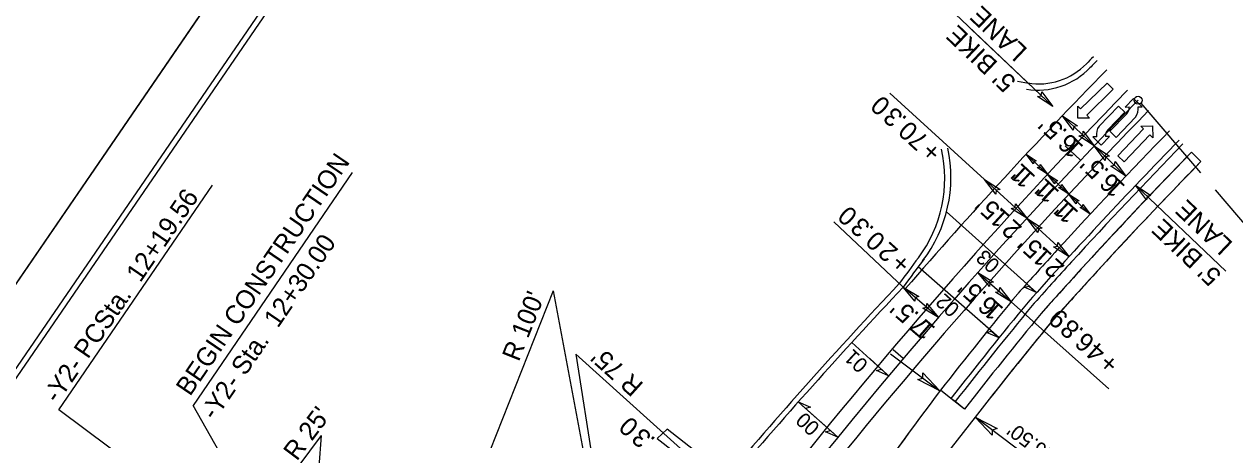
# Model space of a CAD drawing. Extents: x 1975573 to 1977432, y 778300 to 780514.
# Drawn here: x 1976079 to 1976648, y 779581 to 779776 of the extents above; entities that cross this region are included whole.
import ezdxf

# ---------------------------------------------------------------- set-up
doc = ezdxf.new("R2010")
doc.units = 0
for name, color, linetype in [('Prop Conc 2ft 6in Curb and Gutter', 7, 'Continuous'), ('Prop Conc 4in Sidewalk', 7, 'Continuous'), ('Prop Dimension', 7, 'Continuous'), ('Prop Dimension Text', 7, 'Continuous'), ('Prop EOT', 7, 'Continuous'), ('Prop Horizontal Alignment', 7, 'Continuous'), ('Prop Horizontal Alignment Station Label', 7, 'Continuous'), ('Prop Horizontal Alignment Tick Large', 7, 'Continuous'), ('Prop Horizontal Alignment Tick Small', 7, 'Continuous'), ('Prop Lane Arrow CELL', 7, 'Continuous'), ('Prop Lane Lines', 7, 'Continuous'), ('Prop Superelevation  Arrow CELL', 7, 'Continuous'), ('Prop Superelevation Label', 7, 'Continuous'), ('Prop Terminator CELL', 7, 'Continuous'), ('Sheet Cutting Line CELL', 7, 'Continuous'), ('Sheet Plot Border Inside CELL', 7, 'Continuous'), ('Sheet Plot Border Outside CELL', 7, 'Continuous'), ('Sheet Typical CELL', 7, 'Continuous'), ('Typical Terminator CELL', 7, 'Continuous')]:
    doc.layers.add(name, color=color, linetype=linetype)

# ---------------------------------------------------------------- blocks, each defined once
blk = doc.blocks.new('TERMINATOR')
at = {"layer": 'Typical Terminator CELL'}
blk.add_lwpolyline([(-0.469, 0.081), (0, 0), (-0.471, -0.083), (-0.411, 0)], close=True, dxfattribs=at)

msp = doc.modelspace()

# ---------------------------------------------------------------- linework, layer by layer
at = {"layer": 'Prop Conc 2ft 6in Curb and Gutter'}
msp.add_line((1976545.66, 779749.13), (1976550.8, 779748.26), dxfattribs=at)
for centre, radius, start, end in [((1978303.2, 778082.63), 2404.37, 135.73946, 135.84984), ((1976555.6, 779779.15), 31.25, 260.4237, 315.8498), ((1978303.2, 778082.63), 2345.62, 135.73946, 137.60087), ((1976448.91, 779703.56), 62.5, 323.2499, 12.6226), ((1978429.52, 778224.57), 2409.39, 143.24986, 143.60985), ((1978303.2, 778082.63), 2345.62, 137.60087, 138.28391), ((1978239.96, 778006.13), 2403.74, 136.72119, 139.7323), ((1978364.54, 778155.19), 2345.04, 140.59771, 142.01273)]:
    msp.add_arc(centre, radius, start, end, dxfattribs=at)
at = {"layer": 'Prop Conc 4in Sidewalk'}
for p, q in [((1976631.83, 779711.41), (1976627.35, 779715.77)), ((1976631.83, 779711.41), (1976627.35, 779715.77)), ((1976514.33, 779600.08), (1976509.41, 779603.93)), ((1976520.72, 779595.06), (1976514.33, 779600.08)), ((1976380.92, 779585.56), (1976376.28, 779581.25)), ((1976409.06, 779563.62), (1976380.92, 779585.56)), ((1976376.28, 779581.25), (1976404.98, 779558.88))]:
    msp.add_line(p, q, dxfattribs=at)
for points in [[(1976561.18, 779635.59), (1976561.17, 779635.6)], [(1976561.51, 779635.99), (1976561.51, 779635.99)], [(1976520.72, 779595.06), (1976514.33, 779600.08), (1976509.41, 779603.93)], [(1976509.41, 779603.93), (1976509.41, 779603.93)], [(1976520.72, 779595.06), (1976516.3, 779598.53), (1976514.33, 779600.08)]]:
    msp.add_lwpolyline(points, dxfattribs=at)
for centre, radius, start, end in [((1978303.2, 778082.63), 2340, 135.73946, 138.27742), ((1978303.2, 778082.63), 2340, 135.73946, 137.58605), ((1978303.2, 778082.63), 2340, 135.8138, 137.58605), ((1978303.2, 778082.63), 2333.75, 135.73946, 138.27119), ((1978303.2, 778082.63), 2333.75, 135.73946, 137.56744), ((1978303.2, 778082.63), 2340, 137.58605, 138.27742), ((1978303.2, 778082.63), 2340, 137.58605, 138.27742), ((1978303.2, 778082.63), 2333.75, 137.56744, 138.28391), ((1978364.54, 778155.19), 2339.42, 140.6042, 142.01325), ((1978364.54, 778155.19), 2339.42, 140.6042, 142.01325), ((1978364.54, 778155.19), 2339.42, 140.6042, 142.01325), ((1978364.54, 778155.19), 2333.17, 140.6042, 142.01244), ((1978364.54, 778155.19), 2333.17, 140.61692, 142.01244), ((1978303.2, 778082.63), 2333.75, 138.2743, 138.28391), ((1978364.54, 778155.19), 2333.17, 140.6042, 140.60732), ((1978392.04, 778191.34), 2353.66, 143.11825, 144.71902), ((1978392.04, 778191.34), 2353.66, 143.11825, 144.7184), ((1978364.97, 778155.71), 2333.19, 142.02902, 143.82111), ((1978364.97, 778155.71), 2333.19, 142.02902, 143.82111)]:
    msp.add_arc(centre, radius, start, end, dxfattribs=at)
at = {"layer": 'Prop Dimension'}
for p, q in [((1976485.91, 779621), (1976509.14, 779603.58)), ((1976507.11, 779600.86), (1976507.04, 779600.78)), ((1976523.6, 779588.49), (1976523.54, 779588.4)), ((1976561.64, 779564.2), (1976525.64, 779591.2))]:
    msp.add_line(p, q, dxfattribs=at)
at = {"layer": 'Prop Dimension Text'}
for p, q in [((1976516.31, 779780.83), (1976562.16, 779737.26)), ((1976524.02, 779773.51), (1976562.16, 779737.26)), ((1976485.63, 779743.57), (1976530.14, 779702.9)), ((1976581.64, 779718.74), (1976566.69, 779732.95)), ((1976596.59, 779704.54), (1976581.64, 779718.74)), ((1976549.62, 779714.8), (1976559.68, 779705.43)), ((1976549.98, 779684.77), (1976530.14, 779702.9)), ((1976559.68, 779705.43), (1976569.75, 779696.06)), ((1976569.75, 779696.06), (1976579.81, 779686.69)), ((1976601.12, 779700.23), (1976643.6, 779659.86)), ((1976554.56, 779649.78), (1976512.21, 779687.74)), ((1976569.82, 779666.64), (1976549.98, 779684.77)), ((1976459.32, 779683.08), (1976491.9, 779652.41)), ((1976536.92, 779628.55), (1976498.92, 779661.89)), ((1976527.03, 779659.28), (1976542.58, 779645.42)), ((1976327.31, 779650.68), (1976281.28, 779534.47)), ((1976327.31, 779650.68), (1976350.38, 779527.83)), ((1976508.43, 779638.08), (1976491.9, 779652.41)), ((1976588.53, 779604.52), (1976542.61, 779645.46)), ((1976337.97, 779620.81), (1976352.55, 779528.21)), ((1976337.97, 779620.81), (1976407.71, 779558.17)), ((1976218.28, 779582.67), (1976199.52, 779557.67)), ((1976218.28, 779582.67), (1976215.95, 779551.51))]:
    msp.add_line(p, q, dxfattribs=at)
at = {"layer": 'Prop EOT'}
for centre, radius, start, end in [((1978303.2, 778082.63), 2401.88, 135.73946, 135.87087), ((1976555, 779779.1), 34.15, 261.1736, 316.5998), ((1978303.2, 778082.63), 2348.12, 135.73946, 138.28391), ((1976449.17, 779704.12), 65.14, 322.7217, 12.0583), ((1978429.52, 778224.57), 2406.89, 143.22203, 143.61344), ((1978239.96, 778006.13), 2401.24, 136.7176, 139.73317), ((1978364.54, 778155.19), 2347.54, 140.59771, 142.01251), ((1978385.78, 778195.91), 2345.91, 143.11561, 144.72166)]:
    msp.add_arc(centre, radius, start, end, dxfattribs=at)
at = {"layer": 'Prop Horizontal Alignment'}
msp.add_arc((1978303.2, 778082.63), 2375, 135.73946, 152.1381, dxfattribs=at)
at = {"layer": 'Prop Horizontal Alignment Station Label'}
for p, q in [((1976603.63, 779738.89), (1976631.61, 779706.14)), ((1976232.78, 779706.22), (1976158.07, 779596.64)), ((1976094.98, 779594.64), (1976167.22, 779700.3)), ((1976638.47, 779698.11), (1976724.43, 779597.46)), ((1976182.82, 779529.12), (1976094.98, 779594.64)), ((1976197.33, 779527.36), (1976158.07, 779596.64))]:
    msp.add_line(p, q, dxfattribs=at)
msp.add_circle((1976602.29, 779740.2), 1.88, dxfattribs=at)
at = {"layer": 'Prop Horizontal Alignment Tick Large'}
msp.add_line((1976575.24, 779711.98), (1976567.97, 779718.84), dxfattribs=at)
at = {"layer": 'Prop Horizontal Alignment Tick Small'}
msp.add_line((1976491.92, 779618.82), (1976487.15, 779622.87), dxfattribs=at)
at = {"layer": 'Prop Lane Arrow CELL'}
for p, q in [((1976575.25, 779736.11), (1976587.77, 779748.33)), ((1976587.77, 779748.33), (1976590.65, 779745.38)), ((1976590.65, 779745.38), (1976578.13, 779733.16)), ((1976573.91, 779731.84), (1976573.94, 779737.45)), ((1976573.94, 779737.45), (1976575.25, 779736.11)), ((1976593.14, 779737.44), (1976583.95, 779727.98)), ((1976596.1, 779734.56), (1976593.14, 779737.44)), ((1976600.16, 779741.07), (1976596.24, 779737.04)), ((1976596.24, 779737.04), (1976598.09, 779737.07)), ((1976604.15, 779737.2), (1976600.16, 779741.07)), ((1976602.25, 779737.13), (1976604.15, 779737.2)), ((1976579.44, 779731.81), (1976573.91, 779731.84)), ((1976578.13, 779733.16), (1976579.44, 779731.81)), ((1976588.12, 779726.36), (1976596.1, 779734.56)), ((1976596.95, 779733.82), (1976588.97, 779725.62)), ((1976591.93, 779722.75), (1976601.12, 779732.2)), ((1976588.97, 779725.62), (1976591.93, 779722.75)), ((1976592.77, 779714.15), (1976604.91, 779726.76)), ((1976603.56, 779728.06), (1976609.08, 779728.2)), ((1976604.91, 779726.76), (1976603.56, 779728.06)), ((1976609.08, 779728.2), (1976609.23, 779722.59)), ((1976582.82, 779723.06), (1976580.97, 779723.03)), ((1976580.97, 779723.03), (1976584.87, 779719.15)), ((1976584.87, 779719.15), (1976588.83, 779723.14)), ((1976588.83, 779723.14), (1976586.98, 779723.12)), ((1976607.88, 779723.89), (1976595.74, 779711.29)), ((1976609.23, 779722.59), (1976607.88, 779723.89)), ((1976595.74, 779711.29), (1976592.77, 779714.15))]:
    msp.add_line(p, q, dxfattribs=at)
for centre, radius, start, end in [((1976594.02, 779736.71), 4.09, 315.8193, 5.4775), ((1976595.78, 779736.04), 6.57, 324.4954, 9.8071), ((1976589.28, 779724.18), 6.57, 144.4954, 189.8071), ((1976591.04, 779723.51), 4.09, 135.8193, 185.4775)]:
    msp.add_arc(centre, radius, start, end, dxfattribs=at)
at = {"layer": 'Prop Lane Lines'}
for centre, radius, start, end in [((1978303.2, 778082.63), 2395.62, 135.73946, 139.08605), ((1978303.2, 778082.63), 2381.88, 135.73946, 141.94983), ((1978303.2, 778082.63), 2368.12, 135.73946, 141.23948), ((1978303.2, 778082.63), 2354.38, 135.73946, 137.61142), ((1978303.2, 778082.63), 2354.38, 137.61142, 138.28391), ((1978364.54, 778155.19), 2353.79, 140.59771, 142.01248)]:
    msp.add_arc(centre, radius, start, end, dxfattribs=at)
at = {"layer": 'Prop Superelevation  Arrow CELL'}
for p, q in [((1976554.56, 779649.78), (1976545.63, 779657.79)), ((1976536.92, 779628.55), (1976527.9, 779636.46)), ((1976485.02, 779610.65), (1976476.16, 779618.74)), ((1976442.43, 779598.45), (1976451.42, 779590.5)), ((1976461.21, 779581.86), (1976452.21, 779589.81))]:
    msp.add_line(p, q, dxfattribs=at)
for points in [[(1976554.56, 779649.78), (1976548.76, 779652.3), (1976551.12, 779652.87)], [(1976536.92, 779628.55), (1976531.09, 779631), (1976533.44, 779631.6)], [(1976485.02, 779610.65), (1976479.24, 779613.22), (1976481.6, 779613.77)], [(1976442.43, 779598.45), (1976448.25, 779595.97), (1976445.9, 779595.38)], [(1976461.21, 779581.86), (1976455.39, 779584.33), (1976457.74, 779584.92)]]:
    msp.add_lwpolyline(points, close=True, dxfattribs=at)
at = {"layer": 'Prop Superelevation Label'}
for p, q in [((1976485.02, 779610.65), (1976467.77, 779626.41)), ((1976461.21, 779581.86), (1976442.43, 779598.45))]:
    msp.add_line(p, q, dxfattribs=at)
at = {"layer": 'Prop Terminator CELL'}
for points in [[(1976557.05, 779744.12), (1976562.16, 779737.26), (1976554.98, 779742.02), (1976556.79, 779742.36)], [(1976571.81, 779726.09), (1976566.69, 779732.95), (1976573.88, 779728.2), (1976572.06, 779727.85)], [(1976576.53, 779725.61), (1976581.64, 779718.74), (1976574.46, 779723.5), (1976576.27, 779723.85)], [(1976586.76, 779711.88), (1976581.64, 779718.74), (1976588.83, 779713.99), (1976587.01, 779713.64)], [(1976553.07, 779710.26), (1976549.62, 779714.8), (1976554.44, 779711.68), (1976553.23, 779711.43)], [(1976556.22, 779709.97), (1976559.68, 779705.43), (1976554.86, 779708.55), (1976556.07, 779708.79)], [(1976591.48, 779711.4), (1976596.59, 779704.54), (1976589.41, 779709.29), (1976591.22, 779709.64)], [(1976535.39, 779696.13), (1976530.14, 779702.9), (1976537.41, 779698.28), (1976535.6, 779697.9)], [(1976563.14, 779700.89), (1976559.68, 779705.43), (1976564.5, 779702.31), (1976563.3, 779702.07)], [(1976566.29, 779700.6), (1976569.75, 779696.06), (1976564.92, 779699.18), (1976566.13, 779699.43)], [(1976573.2, 779691.52), (1976569.75, 779696.06), (1976574.57, 779692.94), (1976573.36, 779692.7)], [(1976606.24, 779693.37), (1976601.12, 779700.23), (1976608.31, 779695.47), (1976606.49, 779695.13)], [(1976544.73, 779691.53), (1976549.98, 779684.77), (1976542.7, 779689.38), (1976544.51, 779689.76)], [(1976576.35, 779691.24), (1976579.81, 779686.69), (1976574.99, 779689.82), (1976576.2, 779690.06)], [(1976555.22, 779678), (1976549.98, 779684.77), (1976557.25, 779680.15), (1976555.44, 779679.77)], [(1976564.57, 779673.4), (1976569.82, 779666.64), (1976562.54, 779671.25), (1976564.35, 779671.63)], [(1976532.36, 779652.59), (1976527.03, 779659.28), (1976534.36, 779654.76), (1976532.56, 779654.36)], [(1976497.32, 779645.78), (1976491.9, 779652.41), (1976499.29, 779647.98), (1976497.49, 779647.56)], [(1976537.24, 779652.12), (1976542.58, 779645.42), (1976535.24, 779649.95), (1976537.05, 779650.35)], [(1976503, 779644.7), (1976508.43, 779638.08), (1976501.03, 779642.5), (1976502.83, 779642.93)]]:
    msp.add_lwpolyline(points, close=True, dxfattribs=at)
at = {"layer": 'Sheet Cutting Line CELL'}
msp.add_line((1976524.64, 780310.68), (1975572.77, 778921.51), dxfattribs=at)
at = {"layer": 'Sheet Plot Border Inside CELL'}
msp.add_lwpolyline([(1976540.62, 780294.27), (1975598.63, 778919.54), (1976469.01, 778323.15), (1977410.99, 779697.88)], close=True, dxfattribs=at)
at = {"layer": 'Sheet Plot Border Outside CELL'}
msp.add_lwpolyline([(1976524.64, 780310.68), (1975572.77, 778921.51), (1976480.18, 778299.74), (1977432.06, 779688.9)], close=True, dxfattribs=at)
at = {"layer": 'Sheet Typical CELL'}
msp.add_lwpolyline([(1976535.66, 780282.52), (1975687.78, 779045.14), (1976553.95, 778451.63), (1977401.82, 779689.01)], close=True, dxfattribs=at)

# ---------------------------------------------------------------- block references
at = {"layer": 'Prop Dimension'}
for p, xscale, yscale, rotation in [((1976509.14, 779603.58), 24.499999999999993, 24.499999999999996, -36.8736862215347), ((1976525.64, 779591.2), 24.499999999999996, 24.499999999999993, 143.12631377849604)]:
    msp.add_blockref('TERMINATOR', p, dxfattribs=dict(at, xscale=xscale, yscale=yscale, rotation=rotation))

# ---------------------------------------------------------------- texts
msp.add_text("16.50'", height=7, rotation=143.1263, dxfattribs=at).set_placement((1976564.37, 779574.09))
at = {"layer": 'Prop Dimension Text'}
for s, rotation, p in [('LANE', 136.4577, (1976550.78, 779764.09)), ("5' BIKE", 136.4577, (1976545.48, 779749.52)), ('0', 137.5783, (1976486.5, 779738.66)), ('3', 137.5783, (1976492.4, 779733.27)), ('.', 137.5783, (1976494.13, 779731.69)), ('5', 136.4577, (1976567.83, 779727.21)), ('0', 137.5783, (1976499.52, 779726.76)), ('7', 137.5783, (1976504.4, 779722.3)), ("'", 136.4577, (1976562.33, 779732.43)), ('.', 136.4577, (1976569.52, 779725.59)), ('6', 136.4577, (1976574.62, 779720.75)), ('1', 136.4577, (1976577.11, 779718.38)), ('+', 137.5783, (1976510.5, 779716.72)), ('1', 137.0538, (1976552.02, 779706.58)), ('1', 137.0538, (1976554.54, 779704.24)), ("'", 136.4577, (1976581.91, 779713.88)), ('5', 136.4577, (1976587.4, 779708.66)), ('.', 136.4577, (1976589.1, 779707.05)), ("'", 137.0538, (1976549.5, 779708.93)), ('1', 137.0538, (1976563.22, 779699.52)), ('6', 136.4577, (1976594.19, 779702.21)), ('1', 136.4577, (1976596.69, 779699.83)), ("'", 137.0538, (1976560.7, 779701.87)), ('1', 137.0538, (1976565.74, 779697.17)), ("'", 137.5783, (1976532.54, 779694.78)), ('5', 137.5783, (1976538.13, 779689.66)), ('1', 137.0538, (1976572.25, 779689.95)), ('1', 137.0538, (1976574.77, 779687.6)), ('LANE', 136.4577, (1976647.31, 779673.02)), ('0', 138.0674, (1976471.04, 779686.86)), ('3', 138.0674, (1976476.99, 779681.52)), ('1', 137.5783, (1976542.4, 779685.76)), ('.', 137.5783, (1976539.86, 779688.08)), ("'", 137.0538, (1976569.72, 779692.3)), ("5' BIKE", 136.4577, (1976642.01, 779658.45)), ('.', 138.0674, (1976478.73, 779679.95)), ('2', 137.5783, (1976548.2, 779680.46)), ('0', 138.0674, (1976484.16, 779675.07)), ('2', 138.0674, (1976490.01, 779669.82)), ("'", 137.5783, (1976552.53, 779676.5)), ('5', 137.5783, (1976558.13, 779671.39)), ('1', 137.5783, (1976562.4, 779667.49)), ('.', 137.5783, (1976559.86, 779669.81)), ('+', 138.0674, (1976496.15, 779664.3)), ('2', 137.5783, (1976568.2, 779662.19)), ("R 100'", 68.3898, (1976311.15, 779616.98)), ("'", 138.2851, (1976524.29, 779655.86)), ('5', 138.2851, (1976529.95, 779650.82)), ('.', 138.2851, (1976531.69, 779649.26)), ('6', 138.2851, (1976536.94, 779644.59)), ('1', 138.2851, (1976539.51, 779642.3)), ("'", 139.086, (1976492.37, 779646.2)), ('5', 139.086, (1976498.1, 779641.24)), ('.', 139.086, (1976499.87, 779639.71)), ('9', 138.2839, (1976570.09, 779638.54)), ('7', 139.086, (1976504.87, 779635.38)), ('1', 139.086, (1976507.47, 779633.12)), ('8', 138.2839, (1976575.55, 779633.68)), ('.', 138.2839, (1976577.29, 779632.13)), ('6', 138.2839, (1976582.54, 779627.45)), ("R 75'", 138.0674, (1976370.23, 779606.76)), ('4', 138.2839, (1976587.78, 779622.77)), ('+', 138.2839, (1976593.95, 779617.27)), ("R 25'", 53.1295, (1976206.83, 779570.29)), ('0', 138.0674, (1976368.17, 779587.81)), ('3', 138.0674, (1976374.11, 779582.47)), ('.', 138.0674, (1976375.85, 779580.9))]:
    msp.add_text(s, height=8.75, rotation=rotation, dxfattribs=at).set_placement(p)
at = {"layer": 'Prop Horizontal Alignment Station Label'}
for s, rotation, p in [('BEGIN CONSTRUCTION', 55.6943, (1976156.63, 779600.7)), ('-Y2- PCSta.  12+19.56', 55.5805, (1976094.28, 779597.3)), ('-Y2- Sta.  12+30.00', 55.6943, (1976168.24, 779589.27)), ('-L- PTSta.  25+31.27', 55.7257, (1976646.04, 779487.1))]:
    msp.add_text(s, height=8.75, rotation=rotation, dxfattribs=at).set_placement(p)
at = {"layer": 'Prop Superelevation Label'}
for s, rotation, p in [('03', 138.1399, (1976537.87, 779663.57)), ('02', 138.1399, (1976518.93, 779642.9)), ('01', 137.4103, (1976475.85, 779616.6)), ('00', 137.4103, (1976453.14, 779587.01))]:
    msp.add_text(s, height=7, rotation=rotation, dxfattribs=at).set_placement(p)

doc.saveas('drawing.dxf')
